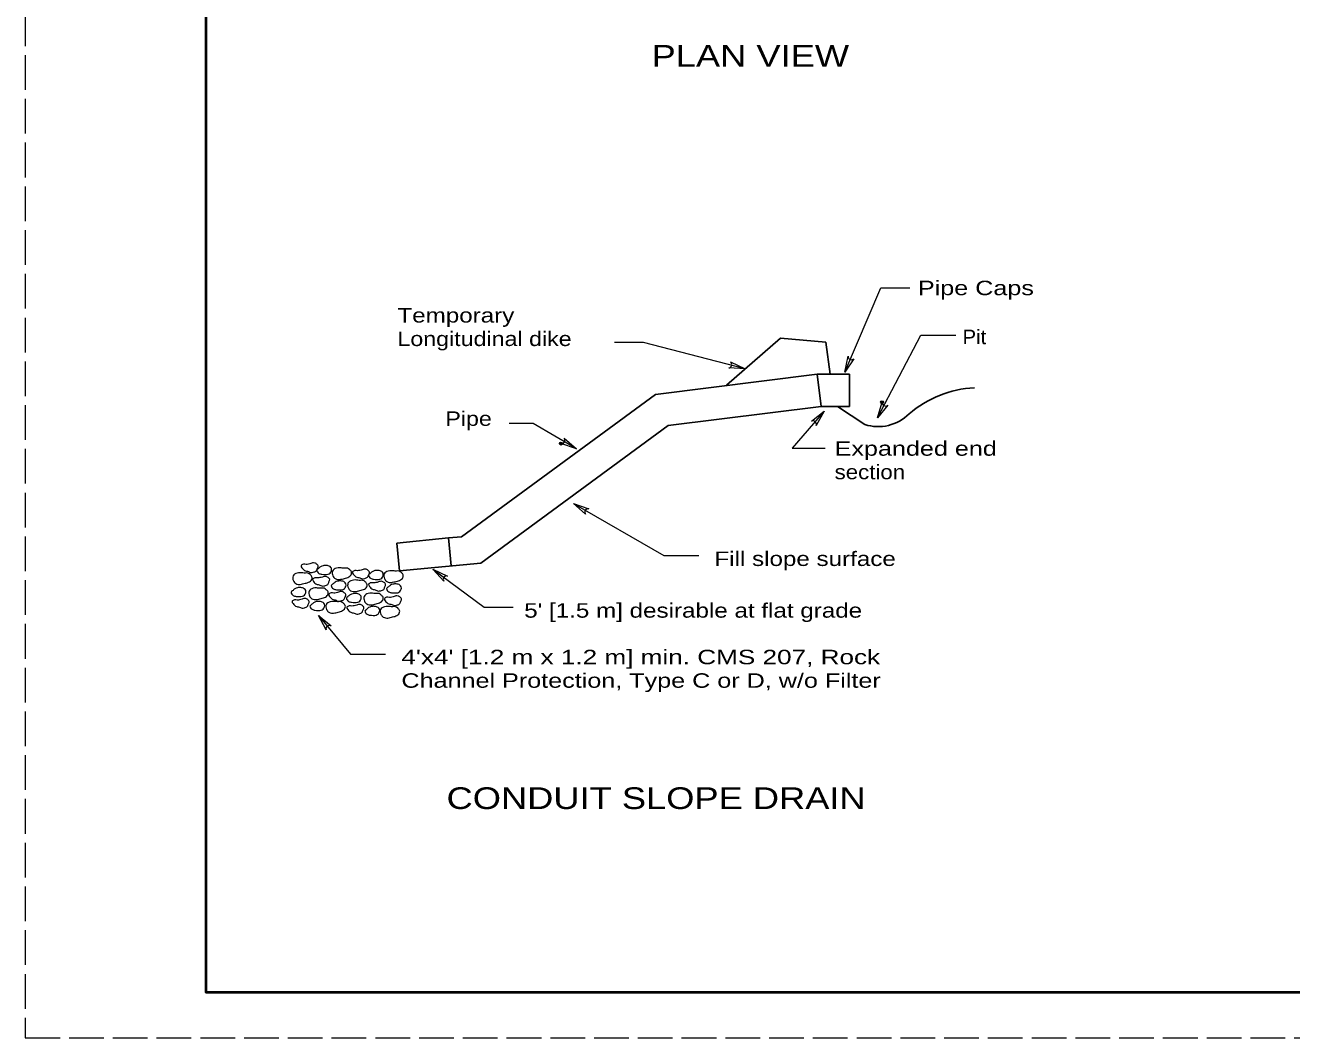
# Model space of a CAD drawing. Extents: x 1043.1 to 1101.1, y 672.4 to 716.4.
# Drawn here: x 1043.14 to 1057.15, y 672.4 to 683.59 of the extents above; entities that cross this region are included whole.
import ezdxf
from ezdxf.enums import TextEntityAlignment as Align

# ---------------------------------------------------------------- set-up
doc = ezdxf.new("R2010")
doc.units = 0
doc.header["$LTSCALE"] = 0.064
doc.header["$PDMODE"] = 32
doc.header["$PDSIZE"] = 0.032
doc.linetypes.add('LONG_DASHED', pattern=[7.5, 6, -1.5])
doc.layers.add('1', color=7, linetype='Continuous', lineweight=13)

msp = doc.modelspace()

# ---------------------------------------------------------------- linework, layer by layer
at = {"layer": '1', "lineweight": 25}
for p, q in [((1050.90025, 679.61067), (1051.49633, 680.13133)), ((1051.99825, 680.08917), (1051.49617, 680.13133)), ((1051.99825, 680.08908), (1052.04883, 679.73458)), ((1052.26133, 679.73458), (1051.90167, 679.73458)), ((1052.26133, 679.73458), (1052.26133, 679.37758)), ((1047.96933, 677.93567), (1050.1165, 679.51017)), ((1051.94633, 679.37758), (1052.26133, 679.37758)), ((1052.12992, 679.37592), (1052.42967, 679.17708)), ((1048.18217, 677.64542), (1050.25375, 679.16475)), ((1047.25342, 677.86633), (1047.82633, 677.92217)), ((1047.82633, 677.92217), (1047.9695, 677.93608)), ((1047.82633, 677.92217), (1047.85617, 677.61383))]:
    msp.add_line(p, q, dxfattribs=at)
at = {"layer": '1'}
for p, q in [((1048.762, 679.18808), (1048.4955, 679.18808)), ((1049.2395, 678.90683), (1048.762, 679.18808))]:
    msp.add_line(p, q, dxfattribs=at)
at = {"layer": '1', "linetype": 'LONG_DASHED'}
msp.add_lwpolyline([(1043.14425, 672.39508), (1077.14425, 672.39508), (1077.14425, 694.39508), (1043.14425, 694.39508)], close=True, dxfattribs=at)
at = {"layer": '1', "lineweight": 25}
for points in [[(1076.64425, 672.89508), (1045.14425, 672.89508), (1045.14425, 693.89508)], [(1050.1165, 679.51017), (1051.90167, 679.73458), (1051.94633, 679.37758), (1050.25375, 679.16475)], [(1048.18217, 677.64542), (1047.28317, 677.55833), (1047.25342, 677.86633)]]:
    msp.add_lwpolyline(points, dxfattribs=at)
at = {"layer": '1', "lineweight": 40}
msp.add_lwpolyline([(1076.64425, 672.89508), (1045.14425, 672.89508), (1045.14425, 693.89508)], dxfattribs=at)
msp.add_lwpolyline([(1076.64425, 672.89508), (1045.14425, 672.89508), (1045.14425, 693.89508)], dxfattribs=at)
at = {"layer": '1'}
for points in [[(1052.20825, 679.75667), (1052.60675, 680.69083), (1052.92767, 680.69083)], [(1051.105, 679.79217), (1049.9835, 680.08375), (1049.66142, 680.08375)], [(1052.57083, 679.25058), (1053.04833, 680.16708), (1053.43692, 680.16708)], [(1050.94308, 679.87067), (1051.105, 679.79217), (1050.92525, 679.80242), (1050.92533, 679.8025)], [(1052.30992, 679.90517), (1052.20825, 679.75667), (1052.245, 679.93292), (1052.24508, 679.93283)], [(1052.68367, 679.39083), (1052.57083, 679.25058), (1052.62108, 679.42342)], [(1051.98225, 679.32358), (1051.62692, 678.91733), (1051.99342, 678.91733)], [(1051.8395, 679.21392), (1051.98225, 679.32358), (1051.89267, 679.1675), (1051.89258, 679.1675)], [(1049.10533, 679.02675), (1049.2395, 678.90683), (1049.0695, 678.966)], [(1049.20617, 678.30283), (1050.20567, 677.73008), (1050.59425, 677.73008)], [(1049.34175, 678.1845), (1049.20617, 678.30283), (1049.37683, 678.24575), (1049.37683, 678.24567)], [(1047.652, 677.57783), (1048.21792, 677.15725), (1048.53992, 677.15725)], [(1047.77267, 677.44425), (1047.652, 677.57783), (1047.81475, 677.50092), (1047.81467, 677.50083)], [(1046.38575, 677.06358), (1046.741, 676.63642), (1047.12975, 676.63642)], [(1046.4715, 676.90533), (1046.38575, 677.06358), (1046.52575, 676.9505), (1046.52575, 676.95042)]]:
    msp.add_lwpolyline(points, dxfattribs=at)
for centre, start, end in [((1050.9203, 679.84022), 277.51399, 53.34012), ((1052.28316, 679.9322), 178.9856, 314.81173), ((1052.65905, 679.41982), 174.5682, 310.39433), ((1051.85658, 679.17995), 340.91278, 116.73891), ((1049.07507, 679.00372), 261.58958, 37.41571), ((1049.37174, 678.20792), 82.27361, 218.09973), ((1047.80516, 677.46397), 75.46854, 211.29467), ((1046.50776, 676.91683), 61.83624, 197.66237)]:
    msp.add_arc(centre, 0.03811, start, end, dxfattribs=at)
at = {"layer": '1', "lineweight": 25}
for centre, major_axis, start_param, end_param in [((1053.70914, 678.37271), (-1.21366, 0), 4.76782544, 5.42002768), ((1052.57801, 679.63914), (-0.48543, 0), 1.26020112, 2.35312872)]:
    msp.add_ellipse(centre, major_axis=major_axis, ratio=0.999895, start_param=start_param, end_param=end_param, dxfattribs=at)
at = {"layer": '1'}
for points in [[(1046.22033, 677.57208), (1046.20367, 677.59142), (1046.19475, 677.61558), (1046.20433, 677.62392), (1046.2195, 677.63217), (1046.25017, 677.62917), (1046.27592, 677.63275), (1046.3035, 677.63942), (1046.32225, 677.64675), (1046.34517, 677.64508), (1046.37267, 677.62917), (1046.38333, 677.61483), (1046.3755, 677.58675), (1046.36142, 677.55783), (1046.32992, 677.54367), (1046.3045, 677.53983), (1046.26583, 677.55375), (1046.2445, 677.55742), (1046.22033, 677.57208)], [(1046.51542, 677.53267), (1046.49283, 677.52125), (1046.46133, 677.51825), (1046.42425, 677.52083), (1046.392, 677.53108), (1046.37583, 677.54667), (1046.36867, 677.56633), (1046.38192, 677.58083), (1046.40992, 677.60408), (1046.43833, 677.61542), (1046.4755, 677.61808), (1046.51442, 677.60533), (1046.52992, 677.58683), (1046.52992, 677.55842), (1046.51542, 677.53267)], [(1046.59825, 677.46408), (1046.57183, 677.47317), (1046.54625, 677.50383), (1046.54242, 677.55675), (1046.5865, 677.58867), (1046.6225, 677.59242), (1046.67925, 677.58867), (1046.70742, 677.58867), (1046.73175, 677.57225), (1046.75192, 677.54808), (1046.743, 677.50675), (1046.72375, 677.49167), (1046.675, 677.47525), (1046.6225, 677.46358), (1046.59825, 677.46408)], [(1046.7885, 677.50267), (1046.77183, 677.52208), (1046.76292, 677.54625), (1046.7725, 677.55467), (1046.78775, 677.56275), (1046.81833, 677.55983), (1046.84392, 677.56342), (1046.8715, 677.57025), (1046.89033, 677.57758), (1046.91325, 677.57583), (1046.94083, 677.55975), (1046.9515, 677.54542), (1046.94375, 677.51742), (1046.92967, 677.48842), (1046.89792, 677.47433), (1046.87267, 677.47042), (1046.834, 677.48442), (1046.81275, 677.48817), (1046.7885, 677.50267)], [(1047.08725, 677.47808), (1047.06475, 677.46667), (1047.03325, 677.46367), (1046.99617, 677.46625), (1046.96392, 677.47642), (1046.94775, 677.49208), (1046.9405, 677.51175), (1046.95392, 677.52625), (1046.98183, 677.54942), (1047.01033, 677.56083), (1047.0475, 677.56342), (1047.08625, 677.55075), (1047.10175, 677.53225), (1047.10175, 677.50383), (1047.08725, 677.47808)], [(1047.17, 677.43125), (1047.1435, 677.44033), (1047.11792, 677.47108), (1047.11417, 677.52408), (1047.15825, 677.55592), (1047.19433, 677.55967), (1047.251, 677.55592), (1047.27925, 677.55592), (1047.3035, 677.53942), (1047.32367, 677.51525), (1047.31475, 677.47392), (1047.2955, 677.45883), (1047.24683, 677.44258), (1047.19433, 677.43083), (1047.17, 677.43125)], [(1046.16117, 677.40942), (1046.13467, 677.41858), (1046.10917, 677.44917), (1046.10533, 677.50208), (1046.14942, 677.53392), (1046.1855, 677.53767), (1046.24217, 677.53392), (1046.27033, 677.53392), (1046.29475, 677.51758), (1046.31492, 677.49325), (1046.306, 677.45208), (1046.28675, 677.43708), (1046.23792, 677.42067), (1046.1855, 677.40892), (1046.16117, 677.40942)], [(1046.34775, 677.42242), (1046.33125, 677.44183), (1046.32233, 677.46592), (1046.33192, 677.47433), (1046.34692, 677.48242), (1046.3775, 677.47967), (1046.40333, 677.48325), (1046.43092, 677.48992), (1046.44967, 677.49725), (1046.4725, 677.49558), (1046.50017, 677.47942), (1046.51083, 677.46525), (1046.503, 677.43725), (1046.489, 677.40833), (1046.45733, 677.39417), (1046.432, 677.39033), (1046.39325, 677.40425), (1046.372, 677.40792), (1046.34775, 677.42242)], [(1046.67567, 677.36125), (1046.653, 677.34983), (1046.6215, 677.34683), (1046.5845, 677.34958), (1046.55233, 677.35975), (1046.53617, 677.37533), (1046.52892, 677.39508), (1046.54233, 677.40958), (1046.57025, 677.43258), (1046.5985, 677.44392), (1046.63575, 677.44667), (1046.67467, 677.43408), (1046.69017, 677.41558), (1046.69017, 677.38708), (1046.67567, 677.36125)], [(1046.76942, 677.32917), (1046.74292, 677.33825), (1046.71733, 677.36892), (1046.7135, 677.42183), (1046.75775, 677.45367), (1046.79383, 677.45742), (1046.85033, 677.45367), (1046.8785, 677.45367), (1046.90292, 677.43733), (1046.923, 677.41317), (1046.91417, 677.37183), (1046.89483, 677.35675), (1046.84617, 677.34042), (1046.79383, 677.32867), (1046.76942, 677.32917)], [(1046.96717, 677.36775), (1046.95042, 677.38725), (1046.9415, 677.41133), (1046.95117, 677.41975), (1046.96625, 677.42783), (1046.99683, 677.42508), (1047.02267, 677.42867), (1047.05025, 677.43533), (1047.06883, 677.44258), (1047.09175, 677.44083), (1047.11933, 677.42483), (1047.13, 677.41067), (1047.12225, 677.38258), (1047.10825, 677.35367), (1047.0765, 677.33942), (1047.05133, 677.33567), (1047.0125, 677.34958), (1046.99133, 677.35325), (1046.96717, 677.36775)], [(1047.28767, 677.32842), (1047.265, 677.31708), (1047.2335, 677.31408), (1047.19642, 677.31667), (1047.16425, 677.32683), (1047.148, 677.34242), (1047.14083, 677.36217), (1047.15417, 677.37667), (1047.18217, 677.39983), (1047.2105, 677.41125), (1047.24775, 677.41383), (1047.28667, 677.40117), (1047.30217, 677.38267), (1047.30217, 677.35425), (1047.28767, 677.32842)], [(1046.23125, 677.28833), (1046.20875, 677.27692), (1046.17717, 677.27392), (1046.14, 677.27658), (1046.10792, 677.28675), (1046.09183, 677.30233), (1046.08467, 677.32208), (1046.09792, 677.33658), (1046.12575, 677.35975), (1046.15425, 677.37117), (1046.19142, 677.37375), (1046.23033, 677.36108), (1046.24575, 677.34258), (1046.24575, 677.31417), (1046.23125, 677.28833)], [(1046.33967, 677.24158), (1046.31317, 677.25067), (1046.2875, 677.28133), (1046.28375, 677.33425), (1046.32783, 677.36625), (1046.36383, 677.36992), (1046.4205, 677.36625), (1046.44875, 677.36625), (1046.473, 677.34975), (1046.49325, 677.32558), (1046.48433, 677.28425), (1046.465, 677.26917), (1046.41633, 677.25283), (1046.36383, 677.24108), (1046.33967, 677.24158)], [(1046.52633, 677.25475), (1046.50967, 677.27417), (1046.50075, 677.29825), (1046.51033, 677.30667), (1046.5255, 677.31483), (1046.55617, 677.31192), (1046.58192, 677.31558), (1046.60933, 677.32225), (1046.62817, 677.32967), (1046.651, 677.32792), (1046.67867, 677.31183), (1046.68933, 677.29758), (1046.6815, 677.26942), (1046.66742, 677.24058), (1046.63575, 677.22658), (1046.61042, 677.22267), (1046.57183, 677.23642), (1046.5505, 677.24025), (1046.52633, 677.25475)], [(1046.84317, 677.22267), (1046.82075, 677.21125), (1046.78917, 677.20825), (1046.752, 677.21092), (1046.71992, 677.22117), (1046.70375, 677.23667), (1046.6965, 677.25625), (1046.70983, 677.27083), (1046.73775, 677.29392), (1046.76625, 677.30533), (1046.80342, 677.30808), (1046.84217, 677.29525), (1046.85767, 677.27683), (1046.85767, 677.24833), (1046.84317, 677.22267)], [(1046.94792, 677.18333), (1046.92133, 677.19242), (1046.89583, 677.22317), (1046.89192, 677.27592), (1046.93617, 677.30783), (1046.97225, 677.31167), (1047.02892, 677.30783), (1047.05717, 677.30783), (1047.08133, 677.29142), (1047.1015, 677.26725), (1047.09267, 677.22608), (1047.07333, 677.21092), (1047.02475, 677.19467), (1046.97225, 677.18283), (1046.94792, 677.18333)], [(1047.14183, 677.20733), (1047.12517, 677.22675), (1047.11625, 677.25075), (1047.12583, 677.25917), (1047.14092, 677.26733), (1047.1715, 677.26442), (1047.19733, 677.26808), (1047.22492, 677.27475), (1047.24375, 677.28208), (1047.26667, 677.28042), (1047.29425, 677.26433), (1047.30492, 677.25008), (1047.29717, 677.22208), (1047.283, 677.19317), (1047.25133, 677.17908), (1047.226, 677.17517), (1047.18733, 677.18908), (1047.166, 677.19283), (1047.14183, 677.20733)], [(1046.12192, 677.17817), (1046.10533, 677.19767), (1046.0965, 677.22175), (1046.10617, 677.23017), (1046.12117, 677.23817), (1046.15175, 677.23525), (1046.1775, 677.23883), (1046.20517, 677.24567), (1046.22383, 677.25292), (1046.24675, 677.25125), (1046.27433, 677.23525), (1046.285, 677.22108), (1046.27725, 677.19292), (1046.26317, 677.16408), (1046.2315, 677.14983), (1046.20617, 677.14608), (1046.16742, 677.15992), (1046.14617, 677.16367), (1046.12192, 677.17817)], [(1046.43892, 677.13508), (1046.41642, 677.12367), (1046.38483, 677.12067), (1046.34775, 677.12333), (1046.31575, 677.13358), (1046.2995, 677.14917), (1046.29233, 677.16883), (1046.30567, 677.18333), (1046.33367, 677.20642), (1046.36192, 677.21783), (1046.39917, 677.22058), (1046.438, 677.20783), (1046.4535, 677.18933), (1046.4535, 677.16083), (1046.43892, 677.13508)], [(1046.52917, 677.09208), (1046.5025, 677.10117), (1046.477, 677.13183), (1046.47317, 677.18475), (1046.51733, 677.21667), (1046.55342, 677.22042), (1046.60992, 677.21667), (1046.63817, 677.21667), (1046.6625, 677.20025), (1046.68275, 677.17608), (1046.67383, 677.13475), (1046.6545, 677.11967), (1046.60575, 677.10325), (1046.55342, 677.09158), (1046.52917, 677.09208)], [(1046.72667, 677.11242), (1046.70992, 677.13183), (1046.701, 677.15592), (1046.71067, 677.16433), (1046.72575, 677.17258), (1046.75633, 677.16967), (1046.78217, 677.17325), (1046.80975, 677.17992), (1046.8285, 677.18725), (1046.85133, 677.18567), (1046.87892, 677.16958), (1046.8895, 677.15525), (1046.88175, 677.12717), (1046.86775, 677.09825), (1046.83617, 677.08408), (1046.81083, 677.08025), (1046.77217, 677.09417), (1046.75083, 677.09783), (1046.72667, 677.11242)], [(1047.04725, 677.08042), (1047.02475, 677.06908), (1046.99317, 677.06608), (1046.956, 677.06875), (1046.92392, 677.07892), (1046.90775, 677.09458), (1046.9005, 677.11425), (1046.91383, 677.12875), (1046.94175, 677.15183), (1046.97025, 677.16325), (1047.00742, 677.16592), (1047.04633, 677.15325), (1047.06175, 677.13475), (1047.06175, 677.10625), (1047.04725, 677.08042)], [(1047.12992, 677.03742), (1047.10342, 677.04642), (1047.07792, 677.07717), (1047.074, 677.13008), (1047.11817, 677.16192), (1047.15433, 677.16567), (1047.21092, 677.16192), (1047.23917, 677.16192), (1047.2635, 677.14558), (1047.28367, 677.12125), (1047.27475, 677.08008), (1047.25542, 677.06483), (1047.20675, 677.04858), (1047.15433, 677.03683), (1047.12992, 677.03742)]]:
    msp.add_spline(points, degree=3, dxfattribs=at)
for p in [(1052.62108, 679.42342), (1049.0695, 678.966)]:
    msp.add_point(p, dxfattribs=at)

# ---------------------------------------------------------------- texts
at = {"layer": '1', "width": 1.25}
for s, p in [('PLAN VIEW', (1051.16383, 683.13508)), ('CONDUIT SLOPE DRAIN', (1050.12183, 674.92417))]:
    msp.add_text(s, height=0.24, dxfattribs=at).set_placement(p, align=Align.CENTER)
at = {"layer": '1'}
for s, width, p in [('Pipe Caps', 1.3, (1053.01742, 680.60783)), ('Temporary', 1.25, (1047.26017, 680.30517)), ('Pit', 1.05, (1053.51133, 680.06617)), ('Longitudinal dike', 1.2, (1047.26017, 680.04517)), ('Pipe', 1.2, (1047.79058, 679.16217)), ('Expanded end', 1.3, (1052.09617, 678.83192)), ('section', 1.15, (1052.09617, 678.57192)), ('Fill slope surface', 1.25, (1050.76667, 677.61242)), ("5' [1.5 m] desirable at flat grade", 1.25, (1048.66275, 677.04067)), ("4'x4' [1.2 m x 1.2 m] min. CMS 207, Rock ", 1.35, (1047.30425, 676.5255)), ('Channel Protection, Type C or D, w/o Filter', 1.3, (1047.30425, 676.2655))]:
    msp.add_text(s, height=0.16, dxfattribs=dict(at, width=width)).set_placement(p)

doc.saveas('drawing.dxf')
